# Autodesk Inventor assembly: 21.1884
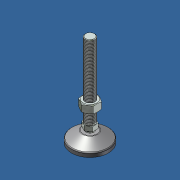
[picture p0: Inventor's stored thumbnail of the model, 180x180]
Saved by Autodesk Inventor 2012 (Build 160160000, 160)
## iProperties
Created: 2007-03
Part Number: 21.1884
Document SubType Name: Assembly
Designer: Andy Moles
Description: LEVELING FOOT M16 60mm BASE
Author: Andy Moles
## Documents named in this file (5)
- C:\Andys Backup Data\ANDY'S INVENTOR\INVENTOR LIBRARIES\PARTS LIBRARY\FEET WHEELS FLOOR FASTENING SUPPORTS\21.1884 LEVELING FOOT M16 60mm BASE.iam
- C:\Andys Backup Data\ANDY'S INVENTOR\INVENTOR LIBRARIES\PARTS LIBRARY\FASTENING ELEMENTS\NUTS\21.1529 M16 HEX NUT.ipt
- C:\Andys Backup Data\ANDY'S INVENTOR\INVENTOR LIBRARIES\PARTS LIBRARY\FEET WHEELS FLOOR FASTENING SUPPORTS\SUBCOMPONENTS\LEVELING FEET SUBCOMPONENTS\PAD 60mm PLASTIC.ipt
- C:\Andys Backup Data\ANDY'S INVENTOR\INVENTOR LIBRARIES\PARTS LIBRARY\FEET WHEELS FLOOR FASTENING SUPPORTS\SUBCOMPONENTS\LEVELING FEET SUBCOMPONENTS\ANTI-SKID PAD 60mm.ipt
- C:\Andys Backup Data\ANDY'S INVENTOR\INVENTOR LIBRARIES\PARTS LIBRARY\FEET WHEELS FLOOR FASTENING SUPPORTS\SUBCOMPONENTS\LEVELING FEET SUBCOMPONENTS\THREADED STUD 16mm SHORTER.ipt
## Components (4 placed, 4 different names)
1. ANTI-SKID PAD 60mm:1 — Insert:1
2. PAD 60mm PLASTIC:1 — Insert:1, Tangent:1, Mate:1
3. THREADED STUD 16mm SHORTER:1 — Tangent:1, Mate:1, Mate:2
4. 21.1529 M16 HEX NUT:1 — Mate:2
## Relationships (4: Mate 2, Insert 1, Tangent 1)
- Insert:1: ANTI-SKID PAD 60mm:1 ↔ PAD 60mm PLASTIC:1
- Tangent:1: PAD 60mm PLASTIC:1 ↔ THREADED STUD 16mm SHORTER:1
- Mate:1: PAD 60mm PLASTIC:1 ↔ THREADED STUD 16mm SHORTER:1
- Mate:2: THREADED STUD 16mm SHORTER:1 ↔ 21.1529 M16 HEX NUT:1
